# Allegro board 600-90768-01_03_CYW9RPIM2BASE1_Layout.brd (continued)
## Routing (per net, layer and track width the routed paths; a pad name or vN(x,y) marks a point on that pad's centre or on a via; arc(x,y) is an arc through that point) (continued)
SD_CLK: length 34.6
  TOP w0.14: v1(105.46,36.14) 105.86,36.54 J10.57
  BOTTOM w0.14: R18.1 123.75,28.83 120.48,32.1 120.28,32.1 120.01,31.83 119.81,31.83 119.61,32.03 119.61,32.23 119.88,32.5 119.88,32.7 118.11,34.47 110.21,34.47 109.15,35.52 108.57,35.52 108.15,35.1 106.15,35.1 105.46,35.79 v1(105.46,36.14)
SD_CMD: length 36.5
  TOP w0.14: J10.62 111.45,35.74 111.99,35.2 v1(111.99,33.96)
  BOTTOM w0.14: v1(111.99,33.96) 117.09,33.96 117.6,33.45 117.6,32.41 117.98,32.03 117.98,31.84 117.6,31.46 117.6,31.27 117.8,31.07 118,31.07 118.37,31.44 118.57,31.44 118.77,31.24 118.77,31.05 118.39,30.67 118.39,30.48 118.59,30.28 118.79,30.28 119.16,30.65 119.36,30.65 119.56,30.45 119.56,30.26 119.18,29.88 119.18,29.68 119.38,29.49 119.58,29.49 119.95,29.86 120.15,29.86 120.35,29.66 120.35,29.47 119.98,29.09 119.98,28.89 120.17,28.7 120.37,28.7 120.74,29.07 120.94,29.07 121.14,28.87 121.14,28.68 120.77,28.3 120.77,28.1 120.96,27.91 121.16,27.91 121.53,28.28 121.73,28.28 122.68,27.33 122.68,26.49 122.54,26.35 122.16,26.35 122.02,26.21 122.02,25.93 122.16,25.79 122.54,25.79 122.68,25.65 122.68,25.37 122.54,25.23 122.16,25.23 122.02,25.09 122.02,24.81 122.16,24.67 122.54,24.67 122.68,24.53 122.68,24.25 122.54,24.12 122.16,24.12 122.02,23.98 122.02,23.7 122.16,23.56 122.54,23.56 122.68,23.42 122.68,23.14 122.54,23 122.16,23 122.02,22.86 122.02,22.58 122.16,22.44 122.54,22.44 122.68,22.3 122.68,22.02 122.54,21.88 122.26,21.88 122.12,21.74 122.12,21.46 122.26,21.32 122.54,21.32 122.68,21.18 R17.1
SD_DAT0: length 32.2
  TOP w0.14: J10.63 106.54,35.34 v1(106.25,35.64)
  BOTTOM w0.14: v1(106.25,35.64) 108.1,35.64 108.4,35.93 109.3,35.93 109.83,35.4 111.51,35.4 111.94,34.98 118.16,34.98 124.92,28.22 R19.1
SD_DAT1: length 28.2
  TOP w0.14: J10.67 108.87,34.54 109.16,34.25 109.16,33.37 v1(108.92,33.12)
  BOTTOM w0.14: v1(108.92,33.12) 109.7,33.12 110.61,32.22 112.97,32.22 114.17,31.01 115.27,31.01 115.82,30.45 115.82,28.4 119.31,24.92 119.31,24.01 119.17,23.87 118.5,23.87 118.36,23.74 118.36,23.46 118.5,23.32 119.17,23.32 119.31,23.18 119.31,22.9 119.17,22.76 118.5,22.76 118.36,22.62 118.36,22.34 118.5,22.2 119.17,22.2 119.31,22.06 119.31,21.78 119.17,21.64 118.5,21.64 118.36,21.5 118.36,21.22 118.5,21.08 119.17,21.08 119.31,20.94 R20.1
SD_DAT2: length 38.2
  TOP w0.14: J10.69 105.87,34.14 v1(105.77,34.04)
  BOTTOM w0.14: R15.1 120.4,19.88 120.26,20.02 119.85,20.02 119.71,20.15 119.71,20.43 119.85,20.57 120.26,20.57 120.4,20.71 120.4,20.99 120.26,21.13 119.85,21.13 119.71,21.27 119.71,21.55 119.85,21.69 120.26,21.69 120.4,21.83 120.4,22.11 120.26,22.25 119.85,22.25 119.71,22.39 119.71,22.67 119.85,22.81 120.26,22.81 120.4,22.95 120.4,23.23 120.26,23.37 119.85,23.37 119.71,23.51 119.71,23.79 119.85,23.93 120.26,23.93 120.4,24.07 120.4,24.35 120.26,24.49 119.85,24.49 119.71,24.63 119.71,24.9 119.85,25.04 120.26,25.04 120.4,25.18 120.4,25.7 119.8,26.3 119.61,26.3 119.21,25.9 119.01,25.9 118.81,26.09 118.81,26.29 119.21,26.69 119.21,26.89 119.01,27.09 118.82,27.09 118.39,26.66 118.19,26.66 118,26.86 118,27.06 118.42,27.48 118.42,27.68 118.22,27.88 118.03,27.88 117.6,27.45 117.4,27.45 117.21,27.65 117.21,27.85 117.63,28.27 117.63,28.47 117.43,28.67 117.24,28.67 116.81,28.24 116.61,28.24 116.42,28.44 116.42,28.64 116.84,29.06 116.84,29.26 116.32,29.78 116.32,31.38 115.09,32.61 110.77,32.61 109.15,34.23 105.96,34.23 v1(105.77,34.04)
SD_DAT3: length 36.7
  TOP w0.14: v1(105.44,35.13) 105.44,35.46 106.06,36.08 106.46,36.08 106.8,35.74 J10.61
  BOTTOM w0.14: R16.1 121.49,26.77 120.57,27.69 120.37,27.69 119.85,27.18 119.66,27.18 119.46,27.38 119.46,27.58 119.97,28.09 119.97,28.29 119.77,28.49 119.58,28.49 119.04,27.95 118.84,27.95 118.64,28.14 118.64,28.34 119.18,28.88 119.18,29.08 118.98,29.28 118.79,29.28 118.25,28.74 118.05,28.74 117.85,28.93 117.85,29.13 118.39,29.67 118.39,29.87 118.19,30.07 118,30.07 117.46,29.53 117.26,29.53 117.06,29.72 117.06,29.92 117.6,30.46 117.6,30.66 115.26,33 110.93,33 109.32,34.62 105.87,34.62 105.44,35.05 v1(105.44,35.13)
SD_DET: length 37.8
  TOP w0.127: v1(131.9,16.89) 130.99,17.81 130.99,19.48 128.42,22.05 117.53,22.05 117.04,22.53 v1(117.04,22.58) ; J10.76 115.21,32.94 115.72,32.44 115.72,31.57 114.87,30.72 v1(114.87,29.77)
  BOTTOM w0.127: v1(117.04,22.58) 114.87,24.75 v1(114.87,29.77) ; R23.1 133.88,15.98 133.88,16.56 133.55,16.89 v1(131.9,16.89)
SD_PWR: length 21.8
  TOP w0.381: C20.1 124.26,3.5 v1(124.26,2.72)
  L03_PWR w0.508: v1(126.97,13.79) 126.97,8.89 124.28,6.2 124.28,2.74 v1(124.26,2.72)
  BOTTOM w0.508: J17.4 v1(124.26,2.72) ; v1(126.97,13.79) 128.04,14.86 128.04,16.33 128.83,17.12 130,17.12 130.26,17.39 U9.1
SD_PWR_ON: length 40.6
  TOP w0.127: J10.75 106.05,32.94 105.77,33.22 104.98,33.22 104.39,32.64 104.39,30.56 v1(104.06,30.23) ; v1(127.03,21.11) 126.57,21.56 117.07,21.56 v1(117.01,21.63)
  BOTTOM w0.127: R24.2 129.42,22.13 129.23,21.95 U9.4 128.36,21.95 127.86,21.95 v1(127.03,21.11) ; v1(104.06,30.23) 104.06,29.62 104.42,29.26 105.59,29.26 105.94,29.62 111.86,29.62 112.11,29.37 112.47,29.37 112.7,29.59 114.15,29.59 114.62,29.12 114.62,24.02 v1(117.01,21.63)
SDA0: length 71.3
  TOP w0.14: v1(118.62,33.17) 121.13,33.17 122,34.04 123.95,34.04 128.49,38.57 128.49,73.72 129.77,75.01 131.9,75.01 133.72,73.19 U3.1 ; J10.82 111.46,31.74 111.79,32.08 113.36,32.08 113.67,31.78 v1(114.2,31.78)
  L04 w0.112: v1(114.2,31.78) 114.66,32.23 117.68,32.23 v1(118.62,33.17)
TR0_TAP: length 34.4
  TOP w0.127: TP12.1 v1(91.08,57.61)
  BOTTOM w0.127: v1(91.08,57.61) 91.08,58.55 91.77,59.23 91.77,60.58 91.49,60.86 91.49,66.04 90.88,66.65 90.88,71.45 90.16,72.17 90.16,75.94 91.11,76.89 93.1,76.89 94.6,78.39 J11.P11
TR1_TAP: length 30.1
  TOP w0.127: TP10.1 v1(91.06,59.69)
  BOTTOM w0.127: J11.P12 99.65,78.69 94.49,78.69 92.94,77.14 91.01,77.14 89.91,76.04 89.91,72.05 90.58,71.37 90.58,66.55 91.06,66.07 v1(91.06,59.69)
TR2_TAP: length 19.2
  TOP w0.127: TP11.1 v1(90.02,64.74)
  BOTTOM w0.127: J11.P13 94.27,78.93 92.75,77.4 90.87,77.4 89.63,76.17 89.63,71.95 90.32,71.26 90.32,66.42 90.02,66.12 v1(90.02,64.74)
TR3_TAP: length 19.7
  TOP w0.127: TP13.1 v1(88.85,61.77)
  BOTTOM w0.127: v1(88.85,61.77) 88.85,65.31 90.07,66.53 90.07,71.15 89.38,71.84 89.38,76.27 91.5,78.39 J11.P14
TRD0_N: length 38.6
  TOP w0.114: v1(101.96,65.85) 102.21,66.1 102.21,66.38 101.3,67.3 101.3,67.89 101.19,68 U7.4 101.19,69.56 101.3,69.67 101.3,71.42 101.78,71.91 101.78,74.09 102,74.32 102.3,74.47 102.3,74.47 102.3,75.04 J11.P2 ; J10.10 110.65,46.14 110.7,46.1 112.5,46.1 113.39,46.98 113.39,50.67 v1(113.11,50.95)
  L04 w0.102: v1(113.11,50.95) 113.34,51.19 113.34,52.24 102.19,63.39 102.19,65.61 v1(101.96,65.85)
TRD0_P: length 38.6
  TOP w0.114: J10.12 110.64,45.74 110.71,45.82 112.62,45.82 113.67,46.86 113.67,50.7 v1(113.92,50.95) ; v1(102.77,65.85) 102.63,65.85 102.49,65.99 102.49,66.5 101.57,67.41 101.57,67.89 101.69,68.01 U7.5 101.69,69.54 101.57,69.65 101.57,71.31 102.06,71.79 102.06,73.98 102.17,74.09 102.47,74.24 102.47,74.24 102.75,74.15 J11.P1
  L04 w0.102: v1(102.77,65.85) 102.54,65.61 102.54,63.54 113.69,52.39 113.69,51.18 v1(113.92,50.95)
TRD1_N: length 39.6
  TOP w0.114: v1(99.52,65.82) 99.78,66.09 99.78,67.88 99.69,67.98 U7.1 99.69,69.56 99.8,69.67 99.8,70.78 99.21,71.36 99.21,74.55 97.89,75.87 J11.P6 ; v1(111.58,50.98) 111.58,51.13 111.46,51.26 111.09,51.26 110.72,50.89 110.72,49.65 111.99,48.38 111.99,47.44 111.57,47.02 110.72,47.02 110.65,46.94 J10.6
  L04 w0.102: v1(99.52,65.82) 99.73,65.61 99.73,63.81 110.2,53.34 110.2,51.93 110.2,51.64 110.61,51.23 111.33,51.23 v1(111.58,50.98)
TRD1_P: length 39.6
  TOP w0.114: J10.4 110.67,47.34 110.72,47.29 111.45,47.29 111.71,47.55 111.71,48.26 110.44,49.53 110.44,51 110.97,51.54 111.33,51.54 v1(111.58,51.79) ; v1(100.35,65.82) 100.19,65.82 100.06,65.95 100.06,67.88 100.19,68 U7.2 100.19,69.54 100.08,69.65 100.08,70.89 99.49,71.48 99.49,74.73 99.76,74.99 100.65,74.99 100.91,74.73 100.91,73.63 J11.P3
  L04 w0.102: v1(111.58,51.79) 111.37,51.58 110.75,51.58 110.55,51.79 110.55,53.49 100.08,63.96 100.08,65.72 100.18,65.82 v1(100.35,65.82)
TRD2_N: length 41.1
  TOP w0.114: v1(96.58,67.35) 96.29,67.06 95.75,67.06 95.58,67.24 95.58,67.89 95.69,68.01 U6.5 95.69,69.54 95.55,69.67 95.55,70.21 96.85,71.5 96.85,74.22 96.05,75.02 95.47,75.02 95.19,74.88 94.68,75.05 J11.P8 ; v1(107.72,50.95) 108,50.67 108,48.92 108.76,48.15 108.76,46.23 108.6,46.07 108.4,46.07 108.33,46.14 J10.9
  L04 w0.102: v1(96.58,67.35) 96.4,67.18 95.87,67.18 95.51,66.82 95.51,65.72 95.68,65.55 95.68,65.55 95.93,65.3 95.93,65.3 107.88,53.35 107.88,51.11 v1(107.72,50.95)
TRD2_P: length 41
  TOP w0.114: v1(108.53,50.95) 108.28,50.7 108.28,49.03 109.04,48.27 109.04,46.12 108.72,45.79 108.37,45.79 108.33,45.74 J10.11 ; J11.P7 95.05,74.31 95.13,74.54 95.53,74.75 95.93,74.75 96.57,74.11 96.57,71.62 95.28,70.32 95.28,69.65 95.19,69.56 U6.4 95.19,68 95.3,67.89 95.3,67.12 95.64,66.78 96.32,66.78 v1(96.58,66.52)
  L04 w0.102: v1(96.58,66.52) 96.27,66.83 96.01,66.83 95.86,66.67 95.86,65.87 96.28,65.45 96.28,65.44 108.23,53.49 108.23,51.26 v1(108.53,50.95)
TRD3_N: length 39.8
  TOP w0.114: v1(94.35,66.45) 94.08,66.72 94.08,67.89 94.19,68 U6.2 94.19,69.54 94.11,69.62 94.11,72.36 94.42,72.68 94.42,74.11 93.82,74.71 92.41,74.71 92.29,74.76 J11.P10 ; J10.5 107.01,46.94 106.96,46.99 105.98,46.99 104.67,48.3 104.67,50.94 105.09,51.36 105.77,51.36 v1(106.02,51.61)
  L04 w0.102: v1(94.35,66.45) 94.13,66.24 94.13,65.27 105.01,54.39 105.01,51.75 105.35,51.41 105.82,51.41 v1(106.02,51.61)
TRD3_P: length 39.9
  TOP w0.114: J10.3 107.01,47.34 106.93,47.27 106.1,47.27 104.95,48.41 104.95,50.82 105.21,51.08 105.74,51.08 v1(106.02,50.8) ; J11.P9 92.21,73.33 92.1,73.44 92.1,74.31 92.21,74.42 93.7,74.42 94.14,73.98 94.14,72.79 93.83,72.48 93.83,69.7 93.69,69.56 U6.1 93.69,68.01 93.8,67.89 93.8,66.72 v1(93.53,66.45)
  L04 w0.102: v1(106.02,50.8) 105.75,51.07 105.21,51.07 104.66,51.61 104.66,54.24 93.78,65.12 93.78,66.2 v1(93.53,66.45)
TXD: length 129.4
  TOP w0.14: R96.2 v1(72.25,33.54)
  L04 w0.112: v1(72.25,33.54) 71.96,33.25 71.96,29.92 71.22,29.18 69.8,29.18 68.41,27.8 42.06,27.8 40.89,26.63 36.37,26.63 35.59,25.84 28.73,25.84 27.68,26.88 18.04,26.88 18.03,26.88 15.57,26.88 12.38,30.07 12.38,59.4 19.78,66.79 19.78,75.56 22.68,78.46 22.68,81.38 23.3,82 v1(23.3,84.16)
  BOTTOM w0.14: U16.23 v1(23.3,84.16)
UART_CTS: length 98.5
  TOP w0.127: SW4.4 SW4.3 v1(9.94,47.5) ; J23.36 54.87,33.16 58.27,29.77 71.88,29.77 72.33,30.21 72.78,30.21 74.6,32.03 74.6,40.5 J30.8
  TOP w0.14: v1(11.2,48.76) 12.34,47.62 33.88,47.62 40.03,41.48 46.71,41.48 48.23,39.95 54.46,39.95 54.87,39.54 J23.36
  BOTTOM w0.14: v1(9.94,47.5) v1(11.2,48.76)
USB2_N: length 82.1
  TOP w0.127: v1(136.98,52.78) 136.73,52.53 136.73,50.37 139.83,47.27 140.54,47.27 140.62,47.34 J5.3
  L05 w0.094: v1(72.98,59.02) 73.23,58.78 73.23,55.88 77.88,51.23 101,51.23 102.6,49.63 113.5,49.63 114.03,49.1 129.9,49.1 132.74,51.95 136.45,51.95 136.75,52.25 136.75,52.55 v1(136.98,52.78)
  BOTTOM w0.127: v1(72.98,59.02) 73.27,59.31 73.27,60.14 73.26,60.15 73.26,60.27 73.14,60.38 U1.4
USB2_P: length 82.1
  TOP w0.127: J5.5 140.62,46.94 140.55,47.02 139.72,47.02 136.47,50.26 136.47,52.6 136.3,52.78 v1(136.17,52.78)
  L05 w0.094: v1(73.81,59.02) 73.48,58.7 73.48,55.95 77.97,51.46 101.09,51.46 101.12,51.43 101.15,51.43 102.72,49.86 113.59,49.86 114.12,49.33 129.8,49.33 132.65,52.17 136.36,52.17 136.53,52.34 136.53,52.65 136.4,52.78 v1(136.17,52.78)
  BOTTOM w0.127: v1(73.81,59.02) 73.52,59.3 73.52,60.27 73.64,60.38 U1.3
USB-UART_VBUS: length 26.4
  TOP w0.254: J47.A9 38.06,82.18 J47.B4 ; J47.A4 40.56,82.18 J47.B9
  TOP w0.305: U29.18 v1(39.52,74.59)
  TOP w0.381: 30.29,76.45 D21.1 ; D21.1 30.29,79.31 ; D21.1 31.82,77.88 ; 24.66,56.91 R302.1 24.13,57.46 ; 25.81,56.56 C144.1 26.54,57.21 ; D26.A v1(47.35,74.88) ; 20.8,55.78 U35.7 23.14,55.78 ; 20.8,57.05 U35.8 23.14,57.05
  L03_PWR w0.381: 41.19,82.23 J47.B9 40.51,81.55 ; 37.77,81.48 J47.B4 38.11,81.55
  BOTTOM w0.381: C172.2 38.18,77.7 ; C172.2 38.18,74.44 ; C172.2 39.11,76.07 ; 41.1,81.65 J47.B9 41.19,82.23
  vias: v1(23.67,56.31) v1(24.18,55.63) v1(24.79,56.29) v1(25.22,55.58) v1(25.76,56.29) v1(40.56,77.5) v1(41.58,78.23) v1(41.58,77.44) v1(42.49,78.03)
USB_PWR: length 71.2
  TOP w0.305: J1.B4 118.46,82.18 J1.A9 ; J1.B9 120.96,82.18 J1.A4
  TOP w0.381: 122.01,76.38 D29.K ; D29.K 122.59,77.06 ; D29.K 122.59,75.7 ; D32.C 120.86,74.97 ; D32.C 120.86,72.81 ; D32.C 122.49,73.89 ; D32.C 119.23,73.89 ; C41.2 121.93,70.59 ; C41.2 120.07,70.59 ; C41.2 121,72.22 ; C41.2 121,68.96
  L03_PWR w0.381: v1(76.83,65.86) 77.85,64.85 79.32,64.85 79.81,65.33 79.81,66.55 80.87,67.61 91.49,67.61 92.72,68.84 105.61,68.84 107.17,70.41 108.71,70.41 110.19,71.88 112.74,71.88 113.32,71.3 117.32,71.3 v1(119.43,69.19)
  L04 w0.381: 118.16,81.48 J1.B4 118.51,81.55 ; 120.91,81.55 J1.B9 121.59,82.23
  BOTTOM w0.381: R1.1 76.87,65.83 v1(76.83,65.86)
  vias: v1(119.46,68.02) v1(120.65,68.02) v1(121.51,77.24) v1(121.79,67.97) v1(121.87,78) v1(122.66,77.62)
USBOTG: length 78.1
  TOP w0.127: J5.1 140.93,47.74 140.34,48.34 140.34,50.93 136.47,54.79 v1(135.08,54.79)
  BOTTOM w0.127: U1.2 74.14,60.03 74.34,59.83 74.92,59.83 75.48,60.4 R1.2 R2.1 76.02,58.5 79.2,55.32 91.06,55.32 92.46,53.92 102.62,53.92 104.06,55.37 114.53,55.37 115.11,55.96 117.63,55.96 118.57,55.02 134.85,55.02 v1(135.08,54.79)
USBRPI_DM: length 22
  TOP w0.127: U30.2 39.19,79.33 39.19,79.53 38.96,79.76 v1(38.9,79.76) 39.18,80.04 39.18,80.4 39.06,80.52 J47.A7
  BOTTOM w0.127: J47.B7 39.45,81.97 39.45,81.79 41.16,80.08 41.16,79.32 40.66,78.82 39.54,78.82 39.19,79.16 39.19,79.46 v1(38.9,79.76) 38.96,79.76 39.2,79.99 39.2,80.23 39.01,80.42 37.72,80.42 37.12,79.82 36.74,79.82 36.62,79.69 36.23,79.69 36.11,79.82 35.73,79.82 35.6,79.69 35.22,79.69 35.09,79.82 34.32,79.82 33.88,80.26 33.7,80.26 33.43,80.53 33.43,80.71 32.92,81.22 32.92,82.25 32.38,82.79 29.9,82.79 29.78,82.66 U16.11
USBRPI_DP: length 21.9
  TOP w0.127: U30.1 39.45,79.33 39.45,79.55 39.65,79.76 v1(39.74,79.76) 39.45,80.05 39.45,80.39 39.56,80.51 J47.A6
  BOTTOM w0.127: J47.B6 39.07,82.23 39.19,82.1 39.19,81.5 39.1,81.4 39.1,81.17 39.22,81.04 39.46,81.04 39.55,81.14 39.73,81.14 40.9,79.97 40.9,79.42 40.55,79.07 39.64,79.07 39.45,79.26 39.45,79.63 39.58,79.76 v1(39.74,79.76) 39.45,80.04 39.45,80.34 39.12,80.67 37.62,80.67 37.02,80.07 34.43,80.07 33.17,81.33 33.17,82.35 32.48,83.04 29.91,83.04 29.79,83.16 U16.10
WL_HOST_WAKE: length 61.4
  TOP w0.127: R37.1 52.09,47.34 51.12,46.37 J23.21 51.12,44.75 v1(49.89,43.51)
  BOTTOM w0.127: J35.5 20.42,47.35 29.87,47.35 30.28,46.94 30.28,41.47 31.83,39.91 31.83,37.61 36.57,32.87 48.21,32.87 52.76,37.41 52.76,39.85 53.03,40.12 53.03,41.03 52.02,42.04 50.9,42.04 49.89,43.05 v1(49.89,43.51)
WL_JTAG_TCK: length 53
  TOP w0.14: v1(57.38,34.49) 57.4,34.52 57.4,34.92 57.37,34.95 J23.46
  BOTTOM w0.14: J38.9 18.59,41.45 27.91,41.45 30.15,39.21 30.15,36.91 36.06,31 50.93,31 54.42,34.49 v1(57.38,34.49)
WL_JTAG_TDI: length 51.1
  TOP w0.14: J23.40 55.87,36.08 56.01,35.94 56.25,35.94 56.39,35.8 56.39,35.52 56.25,35.39 56.01,35.39 55.87,35.25 55.87,34.38 56.01,34.25 v1(56.01,33.38)
  BOTTOM w0.14: v1(56.01,33.38) 56.01,32.97 55.37,32.34 55.37,32.14 56.28,31.23 56.28,31.03 56.08,30.84 55.89,30.84 54.98,31.74 54.78,31.74 54.58,31.54 54.58,31.35 55.49,30.44 55.49,30.24 55.29,30.04 55.09,30.04 54.19,30.95 53.99,30.95 52.86,29.82 35.57,29.82 28.97,36.42 28.97,38.72 27.5,40.18 24.94,40.18 J38.3
WL_JTAG_TDO: length 51.2
  TOP w0.14: J23.38 v1(55.37,33.58)
  BOTTOM w0.14: J38.5 22.83,40.61 27.64,40.61 29.36,38.89 29.36,36.58 35.73,30.21 51.32,30.21 52.23,31.13 52.43,31.13 52.92,30.64 53.12,30.64 53.31,30.84 53.31,31.03 52.83,31.52 52.83,31.72 53.02,31.92 53.22,31.92 53.71,31.43 53.91,31.43 54.11,31.63 54.11,31.82 53.62,32.31 53.62,32.51 53.81,32.71 54.01,32.71 54.5,32.22 54.7,32.22 54.9,32.42 54.9,32.61 54.41,33.1 54.41,33.3 54.69,33.58 v1(55.37,33.58)
WL_JTAG_TMS: length 51.3
  TOP w0.14: J23.48 57.87,34.02 v1(57.78,33.93)
  BOTTOM w0.14: v1(57.78,33.93) 57.71,34.01 55.57,34.01 55.5,34.09 54.58,34.09 51.1,30.61 35.9,30.61 29.76,36.75 29.76,39.05 27.76,41.05 20.73,41.05 J38.7
WL_JTAG_TRST: length 42.8
  TOP w0.14: v1(56.87,33.55) J23.44
  BOTTOM w0.14: J38.1 28.57,36.6 28.57,36.26 35.41,29.43 55.92,29.43 56.87,30.38 v1(56.87,33.55)
WL_NDIS: length 23.8
  TOP w0.127: v1(106.81,23.24) 108.62,25.06 108.62,29.94 108.41,30.15 107.52,30.15 J10.89 ; SW8.3 v1(104.72,10.74)
  BOTTOM w0.127: v1(104.72,10.74) 104.01,11.46 104.01,20.45 v1(106.81,23.24)
WL_REG_ON_3P3: length 136.7
  TOP w0.127: SW8.7 99.64,10.41 99.29,10.77 97.66,10.77 97.51,10.62 97.51,7.32 96.52,6.32 91.19,6.32 86.11,11.4 v1(86.11,13.92) 86.94,13.92 87.3,13.56 88.45,13.56 R38.2 90.08,13.58 R31.2 ; v1(61.29,33.99) 61.29,34.7 60.27,35.71 60.27,36.4 59.87,36.8 J23.56 ; v1(62.29,26.83) 39.19,26.83 38.54,27.48 14.25,27.48 12.8,28.93 12.8,32.51 12.42,32.89 12.42,35.86 11.51,36.77 SW3.3 SW3.4
  BOTTOM w0.127: v1(86.11,13.92) 83.19,13.92 75.16,21.95 71.21,21.95 67.32,25.83 65.23,25.83 64.23,26.83 v1(62.29,26.83) 62.29,30.87 61.62,31.53 61.62,33.65 v1(61.29,33.99)
WL_UART_CTS: length 61.8
  TOP w0.127: R54.2 68.61,34.09 64.18,34.09 62.61,35.65 v1(62.61,36.2) 62.37,36.44 J23.66
  BOTTOM w0.127: v1(62.61,36.2) 61.68,36.2 61.37,35.89 54.17,35.89 54.15,35.87 54.14,35.87 50.58,32.31 36.41,32.31 31.32,37.4 31.32,39.7 29.77,41.26 29.77,46.43 29.59,46.61 24.77,46.61 J35.3
WL_UART_RTS: length 54.9
  TOP w0.127: J23.62 61.37,36.78 v1(61.09,36.5)
  BOTTOM w0.127: J35.4 22.61,46.99 29.69,46.99 30.02,46.66 30.02,41.36 31.58,39.81 31.58,37.5 36.52,32.56 50.47,32.56 54.04,36.13 54.04,36.13 54.22,36.3 60.89,36.3 v1(61.09,36.5)
WL_UART_RXD: length 80
  TOP w0.14: v1(68.45,42.8) 67.54,41.88 64.14,41.88 63.63,41.38 63.63,40.34 63.37,40.08 J23.70 63.37,36.86 63.64,36.59 v1(63.64,36.28)
  BOTTOM w0.14: v1(63.64,36.28) 62.83,35.48 61.18,35.48 61.17,35.48 57.76,35.48 57.75,35.49 54.31,35.49 54.31,35.48 54.3,35.48 50.61,31.79 36.39,31.79 30.94,37.24 30.94,39.54 29.38,41.1 29.38,46.07 29.27,46.18 26.87,46.18 J35.2 ; v1(68.45,42.8) 70.31,42.8 71.79,41.32 82.76,41.32 83.13,40.94 85.87,40.94 86.01,41.09 R57.2
WL_UART_TXD: length 54.8
  TOP w0.14: J23.68 62.87,36.7 63.09,36.48 63.09,36.01 63.98,35.13 v1(63.98,35.13) 67.84,35.13 68.03,34.94 R55.2
  BOTTOM w0.14: v1(63.98,35.13) 63.04,35.13 63,35.08 61.02,35.08 61.01,35.09 54.46,35.09 50.77,31.39 36.22,31.39 30.54,37.07 30.54,39.38 28.27,41.65 J35.1
N17441828: length 1.6
  BOTTOM w0.508: U2.5 80.73,68.56 R4.1
N17442267: length 15.9
  BOTTOM w0.127: U14.31 64.97,60.46 65.13,60.3 65.13,59 66.06,58.06 69.77,58.06 71.8,60.1 71.8,62.84 73.14,64.18 U1.7
N17442276: length 14.8
  BOTTOM w0.127: U1.6 72.64,64.06 71.53,62.94 71.53,60.25 69.63,58.36 66.16,58.36 65.47,59.05 U14.30
N17442959: length 9.6
  BOTTOM w0.127: Y1.3 60.28,54.95 61.32,55.98 63.6,55.98 63.94,56.32 63.94,58.47 63.67,58.74 C8.1 63.67,59.61 64.47,60.4 U14.32
N17443006: length 9.6
  BOTTOM w0.127: Y1.1 61.98,56.93 62.5,56.41 63.45,56.41 63.58,56.54 63.58,56.82 63.42,56.97 62.99,56.97 62.89,57.07 62.89,57.33 63.02,57.45 63.4,57.45 63.52,57.58 63.52,57.78 63.42,57.89 63.09,57.89 62.99,57.99 62.99,58.17 63.14,58.32 63.37,58.32 63.45,58.4 63.45,58.6 63.23,58.81 62.88,58.81 62.76,58.93 C7.1 62.76,59.79 63.17,60.2 63.63,60.2 63.97,60.54 U14.33
N17443696: length 3.1
  BOTTOM w0.127: R3.2 60.89,60.15 62.43,60.15 62.97,60.68 U14.35
N17444208: length 1.8
  BOTTOM w0.127: U14.24 68.17,63.4 68.32,63.25 R6.1
N17444213: length 2.6
  BOTTOM w0.127: U14.22 67.91,64.4 69.03,65.51 R7.1
N17444218: length 1.7
  BOTTOM w0.305: R8.1 67.46,59.97 66.47,60.96 U14.28
N17444223: length 1.9
  BOTTOM w0.127: R10.1 68.49,62.37 67.96,62.9 U14.25
N17463017: length 7.5
  TOP w0.127: C53.1 97.38,70.59 98.08,71.28 J11.P5
  BOTTOM w0.127: J11.P4 98.08,74.6 J11.P5
N17463374: length 30.8
  TOP w0.127: R13.2 91.05,69.17 89.89,70.33 v1(88.87,70.33)
  BOTTOM w0.127: v1(88.87,70.33) 88.67,70.33 88.09,70.92 88.09,76.91 88.36,77.18 88.36,78.17 88.09,78.44 88.09,82.43 90.53,84.88 100.14,84.88 J11.P16
N17463377: length 20.8
  TOP w0.127: R14.2 90.11,69.51 89.94,69.67 v1(89.15,69.67)
  BOTTOM w0.127: J11.P18 90.8,85.65 87.83,82.68 87.83,78.64 87.15,77.95 87.15,77.24 87.83,76.56 87.83,70.71 88.87,69.67 v1(89.15,69.67)
N17465158: length 1.5
  TOP w0.203: R21.1 137.91,9.1 D14.C
N17465213: length 6.2
  TOP w0.203: v1(132.28,8.26) 132.28,9.3 U8.4 ; v1(135.48,8.64) 135.94,9.09 R21.2
  BOTTOM w0.203: v1(132.28,8.26) 135.1,8.26 v1(135.48,8.64)
N17469381: length 3.5
  BOTTOM w0.127: J17.9 131.55,15.68 131.85,15.98 R23.2
N17469410: length 3.4
  BOTTOM w0.127: J17.10 133.01,15.02 R22.2
N17494894: length 2.8
  TOP w0.155: J23.53 59.12,47.22 59.59,47.69 R50.1
N17494904: length 2.9
  TOP w0.127: R46.1 57.78,48.06 58.06,47.78 58.06,47.4 57.73,47.06 57.73,46.59 57.62,46.48 J23.47
N17494909: length 2.9
  TOP w0.127: R47.1 58.61,48.04 58.34,47.78 58.34,47.28 58.01,46.95 58.01,46.59 58.12,46.48 J23.49
N17494920: length 2.8
  TOP w0.127: R40.1 54.47,48.1 54.73,47.83 54.73,46.59 54.62,46.48 J23.35
N17494923: length 2.8
  TOP w0.127: J23.37 55.12,46.48 55.01,46.59 55.01,47.8 55.29,48.08 R41.1
N17494926: length 2.8
  TOP w0.127: R42.1 56.12,48.07 56.36,47.83 56.36,47.32 56.23,47.19 56.23,46.59 56.12,46.48 J23.41
N17494929: length 2.9
  TOP w0.127: R43.1 56.95,48.04 56.64,47.73 56.64,47.21 56.51,47.08 56.51,46.59 56.62,46.48 J23.43
N17499052: length 2.7
  TOP w0.155: R28.1 48.12,46.64 J23.9
N17499057: length 2.6
  TOP w0.155: R29.1 47.85,47.4 48.62,46.63 J23.11
N17499218: length 2.4
  TOP w0.155: J23.13 49.12,46.86 48.69,47.3 R30.1
N17499237: length 2.3
  TOP w0.155: J23.15 49.62,47.65 R32.1
N17499256: length 2.3
  TOP w0.155: R35.1 50.39,46.91 50.12,46.64 J23.17
N17499275: length 2.5
  TOP w0.155: J23.19 50.62,46.48 51.25,47.11 R36.1
N17499655: length 14.6
  TOP w0.155: R49.2 68.46,32.22 67.97,32.72 60.81,32.72 59.36,34.16 59.36,35.79 58.87,36.28 J23.52
N17504773: length 1.3
  TOP w0.127: D15.A 33.27,7.33 R58.2
N17512684: length 5.8
  BOTTOM w0.381: R64.1 35.51,21.15 U12.5 33.42,18.69 R61.2 R62.2
N17512777: length 2.3
  BOTTOM w0.381: C35.1 35.52,26.49 34.62,26.49 34.27,26.14 U12.4
N17512799: length 1.5
  BOTTOM w0.381: U12.1 29.58,26.17 C27.1
N17512803: length 0.9
  BOTTOM w0.381: R60.1 C27.2
N17512813: length 21.3
  TOP w0.381: v1(27.19,25.41) 27.84,24.77 27.84,21.87 30.05,19.66 v1(30.05,16.33)
  BOTTOM w0.381: 28.93,21.15 U12.8 29.61,20.12 ; L1.1 29.58,16.29 ; L1.1 26.67,16.29 ; L1.1 28.13,19.12 ; L1.1 28.13,13.46 ; R60.2 v1(27.19,25.41)
N17512829: length 2.7
  BOTTOM w0.381: U12.6 32.15,19.84 C229.1 32.16,19.41 R63.1
N17540958: length 16.9
  TOP w0.254: v1(95.66,16.51) 95.23,16.08 U10.7
  TOP w0.305: v1(94.87,11.68) 95.56,11.68 96.02,12.15 R26.1 C21.2 95.97,13.58 U10.2 ; v1(91.72,13.36) 91.94,13.58 U10.15 ; U10.1 93.85,12.63 v1(94.09,12.38)
  BOTTOM w0.508: v1(94.87,11.68) 94.79,11.68 v1(94.09,12.38) 92.22,12.38 91.72,12.89 v1(91.72,13.36) 91.72,14.45 93.78,16.51 v1(95.66,16.51)
N17540970: length 2.2
  TOP w0.305: R27.1 C22.1 93.32,12.06 93.35,12.09 U10.16
N17541044: length 1.7
  TOP w0.127: R31.1 90.96,13.58 91.47,14.08 U10.14
N17541046: length 1.5
  TOP w0.127: R33.1 90.96,14.58 U10.13
N17541095: length 1.7
  TOP w0.127: U10.12 91.45,15.08 90.99,15.54 R34.1
N17548832: length 50.8
  TOP w0.127: J23.8 47.87,36.66 57.23,27.3 81.32,27.3 85.45,31.42 85.45,31.42 89.14,35.12 J25.2
N17548852: length 51.2
  TOP w0.127: J25.4 80.16,27.55 57.45,27.55 48.37,36.63 J23.10
N17549259: length 16.6
  TOP w0.127: J23.50 58.37,33.02 60.05,31.34 67.87,31.34 68.27,30.94 R48.2
N17549874: length 8.7
  TOP w0.127: SW2.1 v1(5.79,22.72) SW2.2
  BOTTOM w0.127: R44.2 5.79,23.4 v1(5.79,22.72)
N17549924: length 8.9
  TOP w0.127: SW3.2 1.98,32.26 v1(5.79,32.26) 9.93,32.26 SW3.1
  BOTTOM w0.127: v1(5.79,32.26) R45.2
N17560700: length 3.1
  TOP w0.127: J23.23 51.62,46.44 52.22,47.04 52.73,47.04 52.97,47.28 R39.1
N17563208: length 8.8
  TOP w0.127: SW4.2 5.84,41.81 v1(5.84,41.81) 9.94,41.81 SW4.1
  BOTTOM w0.127: v1(5.84,41.81) R52.2
N17565806: length 52.1
  TOP w0.127: J23.12 48.87,36.53 57.6,27.81 77.43,27.81 83.6,33.97 83.6,34.03 87.4,37.84 87.4,38.71 88.89,40.2 J25.6
N17565868: length 53.5
  TOP w0.127: J25.8 88.63,41.1 87.81,41.1 86.84,40.13 86.84,37.83 83.34,34.33 83.34,34.08 77.33,28.06 57.75,28.06 49.37,36.44 J23.14
N17568318: length 21.2
  BOTTOM w0.14: R15.2 120.4,17.55 114.63,11.79 114.63,7.59 118.37,3.85 J17.1
N17568347: length 22.7
  BOTTOM w0.14: J17.2 122.06,4.76 121.87,4.95 118.01,4.95 115.06,7.9 115.06,11.51 118.9,15.34 119.23,15.34 121.49,17.6 R16.2
N17568375: length 22.8
  BOTTOM w0.14: R17.2 122.66,18.5 122.66,17.48 119.91,14.73 119.02,14.73 116.84,12.55 116.84,6.68 118.14,5.38 122.61,5.38 123.16,4.83 J17.3
N17568415: length 24.9
  BOTTOM w0.14: J17.5 125.36,4.92 124.46,5.82 118.34,5.82 117.37,6.78 117.37,12.37 119.1,14.1 120.37,14.1 123.75,17.48 R18.2
N17569067: length 27.2
  BOTTOM w0.14: J17.7 127.56,5.43 126.75,6.25 118.75,6.25 117.86,7.14 117.86,12.04 119.43,13.61 120.9,13.61 124.92,17.63 R19.2
N17569095: length 31.2
  BOTTOM w0.14: R20.2 119.31,17.2 114.17,12.06 114.17,7.42 119.51,2.08 127.13,2.08 127.71,2.67 128.37,2.67 128.66,2.96 J17.8
N17573256: length 2.9
  BOTTOM w0.381: R62.1 34.57,16.39 35.03,15.92 SW5.3
N17579667: length 10.9
  TOP w0.127: U3.5 147.71,71.24 148.34,70.61 148.34,66.63 J9.4
N17579869: length 12.7
  TOP w0.127: J9.3 151.6,65.85 149.81,67.64 149.81,70.56 148.49,71.88 146.36,71.88 U3.6 145.5,71.89 144.96,71.34 R11.2
N17596444: length 36.9
  TOP w0.127: J23.34 54.37,33.22 58.13,29.46 71.98,29.46 72.47,29.95 72.92,29.95 74.9,31.92 74.9,38.26 J30.6
N17596453: length 35.3
  TOP w0.127: J30.4 75.18,36.01 75.18,31.8 73.03,29.64 72.54,29.64 72.07,29.17 57.97,29.17 53.87,33.26 J23.32
N17596462: length 35.2
  TOP w0.127: J30.2 75.92,34.2 75.92,31.14 74.1,29.32 72.6,29.32 72.16,28.88 57.78,28.88 51.37,35.29 J23.22
N17603435: length 4.7
  TOP w0.381: v1(82.52,60.61) 82.55,60.63 v1(84.1,60.63)
  BOTTOM w0.381: v1(84.1,60.63) 84.1,60.25 83.91,60.06 U15.1 ; v1(82.52,60.61) R69.1 C52.2
N17603462: length 6.6
  BOTTOM w0.381: U15.6 83.01,57.32 82.26,58.07 82.26,59.15 83.48,60.36 R70.1
  BOTTOM w0.508: R70.1 C51.1
N17711071: length 2.7
  BOTTOM w0.381: SW5.1 33.19,15.92 33.51,16.24 R61.1
N17724540: length 3.6
  BOTTOM w0.127: R82.2 72.85,18.51 C55.1 R85.1 72.83,16.13 C57.1
N17724607: length 3.3
  BOTTOM w0.127: C58.1 R84.1 69.07,17.14 C56.1 69.07,19.42 R83.2
N17727243: length 20.3
  BOTTOM w0.127: C57.2 70.87,14.66 U18.2 72.63,14.64 76.66,10.62 83.77,10.62 85.29,9.09 85.29,7.01 J46.3
N17727252: length 10.5
  TOP w0.127: v1(69.58,14.64) v1(74.33,14.64)
  BOTTOM w0.127: v1(69.58,14.64) U18.1 70.16,15.34 69.93,15.57 69.93,16.1 C58.2 ; v1(74.33,14.64) 77.74,14.64 J46.2
N17754557: length 15.9
  TOP w0.127: TP33.1 39.09,60.81 39.09,62.03 44.4,67.34 44.4,70.97 44.02,71.34 U29.7
N17754588: length 13
  TOP w0.127: U29.8 44.18,71.84 44.68,71.34 44.68,67.06 40.01,62.38 TP34.1
N17760781: length 20.7
  TOP w0.381: C144.2 25.56,58.31 R302.2 v1(23.84,58.31) ; R297.1 23.71,50.03 C139.2 22.53,51.21 v1(22.48,51.26) 22.13,51.61 20.56,51.61 19.78,52.38 R321.1
  BOTTOM w0.381: v1(23.84,58.31) 22.48,56.95 v1(22.48,51.26)
N17761001: length 1.4
  BOTTOM w0.127: Q14.D 46.48,68.82 R373.1
N17761005: length 2.6
  TOP w0.127: v1(48.18,68.81) 48.18,69.41 D26.C
  BOTTOM w0.127: R373.2 v1(48.18,68.81)
N17763457: length 1.4
  BOTTOM w0.508: C210.1 38.57,44.01 U33.14
N17763461: length 7.5
  BOTTOM w0.254: 39.38,42.76 C210.2
  BOTTOM w0.381: 37.4,36.21 L5.1 ; L5.1 35.77,37.59 ; L5.1 37.4,38.97
  BOTTOM w0.508: U33.13 39.38,42.76 ; C210.2 39.42,42.04
N17763467: length 7.5
  BOTTOM w0.381: L5.2 42.5,38.97 ; L5.2 42.5,36.21 ; L5.2 44.13,37.59
  BOTTOM w0.508: 40.79,42.03 C197.2 U33.12
N17763564: length 1.4
  BOTTOM w0.508: U33.11 41.63,43.97 C197.1
N17763650: length 23.3
  L03_PWR w0.381: v1(41.25,49.43) 41.25,48.74 39.7,47.19 35.56,47.19 v1(35.31,46.94)
  BOTTOM w0.381: 41.98,48.87 C195.1 ; C195.1 41.98,49.93 ; C195.1 41.42,49.4 ; 43.6,62.09 R383.1 42.67,63.07 ; C192.1 41.87,54.32 ; C192.1 41.87,52.36 ; C192.1 41.09,53.34 ; 41.87,50.2 C191.1 ; C191.1 41.87,52.16 ; C191.1 41.09,51.18 ; 41.02,58.01 C185.P ; C185.P 43.05,59.09 ; C185.P 43.05,56.93 ; R399.1 34.98,47.26 v1(35.31,46.94)
  BOTTOM w0.508: U33.3 41.49,48.7
N17763766: length 4.8
  BOTTOM w0.229: U33.15 36.56,44.5 ; 36.56,44.5 36.56,45.2 36.86,45.49 37.7,45.49 U33.17 ; 36.56,44.5 C224.2
N17763790: length 3
  BOTTOM w0.254: R399.2 36.65,47.73 36.88,47.5 U33.21
  BOTTOM w0.305: R399.2 R403.1
N17763820: length 2.8
  BOTTOM w0.229: C225.2 36.54,46 U33.18
N17763850: length 1.5
  BOTTOM w0.229: R384.2 43.25,45.09 43.15,45 U33.9
N17767575: length 7.9
  TOP w0.127: J1.A5 120.46,80.05 121.18,79.32 124.99,79.32 125.91,78.41 R404.2
N17767581: length 15.1
  TOP w0.127: R65.2 v1(116.38,78.46)
  L04 w0.127: J1.B5 118.91,83.93 118.36,84.48 114.15,84.48 113.56,83.9 113.56,80.01 115.11,78.46 v1(116.38,78.46)
N17769646: length 18.2
  TOP w0.127: U29.12 45.23,73.84 46,73.08 46,66.45 43.94,64.39 43.94,61.85 42.6,60.5 TP37.1
N17769649: length 16.3
  TOP w0.127: TP36.1 45.19,65.24 46.28,66.33 46.28,73.43 45.14,74.57 45.14,74.59 U29.13
N17801368: length 4.9
  TOP w0.127: J5.6 144.12,46.99 144.72,46.99 144.86,47.13 144.86,47.13 145.65,47.93 146.73,47.93 146.73,47.92 147.6,47.92 R406.2
N17848252: length 3.8
  TOP w0.127: R408.1 15.59,67.96 16.4,68.77 SW10.1
N17848257: length 2.2
  TOP w0.127: SW10.5 16.4,74.8 R400.2
N17849598: length 2.2
  TOP w0.127: R398.2 21.4,74.8 SW10.7
N17880549: length 1.1
  BOTTOM w0.381: C36.1 R63.2
N174866950: length 1.8
  TOP w0.203: R12.1 137.19,4.15 D13.C

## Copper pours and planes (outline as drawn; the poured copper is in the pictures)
1.8V on L03_PWR: 111.3,30.58 111.96,30.58 112.67,29.87 112.67,29.74 112.27,29.34 111.3,29.34 111.07,29.57 111.07,30.35
3.3V on L03_PWR: outline of 92 points within 52.4,9.96 132.36,88.24 ; 4 cut-outs
5V_IN on BOTTOM: 34.9,68.25 38.46,68.25 38.81,67.89 38.81,67.18 38.53,67.18 38.35,67.01 38.35,66.73 38.63,66.73 39.73,65.63 41.88,65.63 42.04,65.48 42.04,64.16 39.79,61.91 39.79,49.47 38.89,48.56 38.89,45.52 38.86,45.49 38.4,45.49 38.38,45.52 38.38,47.98 38.28,48.08 38.48,48.29 38.48,48.44 38.1,48.44 38.02,48.51 38.02,49.58 37.72,49.89 37.72,54.2 35.64,56.29 35.64,63.12 34.52,64.24 34.52,67.87 ; 3 cut-outs
GND on L03_PWR: 148.79,89.66 149.1,89.36 149.1,88.8 149.81,88.8 150.52,89.51 150.4,89.63 153.15,88.26 154.42,85.46 154.33,85.55 153.62,84.84 153.62,84 154.23,84 154.43,83.79 154.43,5.08 153.09,1.85 149.86,0.51 5.08,0.51 1.85,1.85 0.51,5.08 0.51,85.09 1.85,88.32 5.08,89.66 ; 16 cut-outs
GND_EARTH on BOTTOM: 32.08,89.59 126.36,89.59 126.92,89.03 126.92,85.34 125.73,84.15 125.73,82.02 125.07,81.36 123.75,81.36 123.24,81.86 123.24,82.52 123.29,82.47 123.55,82.47 123.6,82.52 123.6,82.73 123.39,82.73 123.24,82.88 123.23,82.87 122.3,83.79 113.03,83.79 112.47,84.35 112.47,86.16 111.2,87.43 88.39,87.43 87.22,86.26 87.22,75.16 86.49,74.42 82.93,74.42 82.4,74.96 82.4,80.9 81.43,81.86 74.22,81.86 73.03,80.67 73.03,75.39 72.9,75.26 72.52,75.26 72.52,75.21 72.82,74.9 72.37,74.45 72.28,74.32 72.18,74.21 72.16,74.1 72.26,74.04 72.38,74.03 72.61,74.26 72.61,74.28 72.75,74.49 72.96,74.63 72.99,74.64 73.02,74.68 73.02,74.87 72.98,74.95 72.89,74.96 72.87,74.95 73.03,75.11 73.03,74.68 71.78,73.43 71.78,73.61 71.73,73.66 70.97,73.66 70.97,73.25 70.69,72.97 64.8,72.97 63.17,74.6 63.17,82.58 62.26,83.49 54.48,83.49 53.9,82.91 53.9,74.47 52.73,73.3 49.53,73.3 48.84,73.99 48.84,83.67 48.23,84.28 32.87,84.28 31.32,85.83 31.32,88.82
VBUS_OUT on TOP: 25.96,55.02 20.93,55.02 20.6,54.69 20.6,52.63 20.9,52.32 24.26,52.32 24.69,51.89 24.69,50.62 25.17,50.14 29.24,50.14 29.59,50.5 29.59,51.38
VBUS_OUT on BOTTOM: 39.17,66.88 39.17,69.19 39.5,69.52 42.21,69.52 42.81,68.92 42.81,66.81 42.47,66.47 39.57,66.47
VBUS_OUT on BOTTOM: 29.16,31.95 29.16,28.4 30.43,27.13 30.43,25.35 31.32,25.35 31.32,27.38 32.59,28.65 32.59,31.01 31.06,32.54 29.74,32.54
VBUS_OUT on L03_PWR: 33.15,52.04 42.9,61.8 42.9,68.68 42.09,69.49 39.67,69.49 38.56,68.38 38.56,61.32 28.96,51.71 27.23,51.71 26.11,50.6 26.11,49.5 30.07,45.54 30.07,28.91 30.51,28.47 32.66,28.47 33.15,28.96
VDD_5V on BOTTOM: 45.26,61.42 44.83,61.85 44.83,67.16 45.21,67.54 48.59,67.54 49.02,67.11 49.02,61.93 48.51,61.42
VDD_5V on L03_PWR: 104.59,32.65 105.03,33.1 105.92,33.1 106.3,32.72 106.3,30.18 106.02,29.9 104.8,29.9 104.59,30.11
VDD_REG_5V on BOTTOM: 17.09,62.05 17.09,59.13 17.48,58.75 22.3,58.75 22.81,59.26 22.81,62.05 22.3,62.56 17.6,62.56
VDD_REG_5V on BOTTOM: 49.63,64.21 49.63,61.95 50.16,61.42 52.65,61.42 53.09,61.85 53.09,64.31 52.76,64.64 50.06,64.64
VDD_REG_5V on L03_PWR: 18.14,61.24 18.14,54.08 19.86,52.35 26.64,52.35 27.08,52.78 28.02,52.78 35.56,60.33 35.56,67.94 37.97,70.36 43.87,70.36 44.65,69.57 44.65,64.14 46.23,62.56 49.63,62.56 50.8,61.39 52.73,61.39 53.37,62.03 53.37,64.8 52.65,65.51 47.88,65.51 46.81,66.57 46.81,73.03 45.59,74.24 37.74,74.24 33.17,69.67 33.17,61.39 26.57,54.79 23.37,54.79 21.08,57.07 21.08,61.24 20.45,61.87 18.77,61.87
(no net) on TOP: 125.32,89.66 149.86,89.66 153.09,88.32 154.43,85.09 154.43,5.08 153.09,1.85 149.86,0.51 5.08,0.51 1.85,1.85 0.51,5.08 0.51,85.09 1.85,88.32 5.08,89.66 33.48,89.66 33.48,83.85 45.21,83.85 45.21,89.66 114.12,89.66 114.12,84.05 125.32,84.05 ; 132 cut-outs
(no net) on BOTTOM: 0.51,85.09 1.85,88.32 5.08,89.66 149.86,89.66 153.09,88.32 154.43,85.09 154.43,67.31 154.25,67.13 153.7,67.13 153.47,67.36 153.47,67.51 153.11,67.15 153.11,66.9 153.26,66.75 154.43,66.75 154.43,5.08 153.09,1.85 149.86,0.51 5.08,0.51 1.85,1.85 0.51,5.08 ; 152 cut-outs
EXT_5V on BOTTOM: 16.33,82.25 21.36,82.25 23.19,80.42 23.19,64.21 22.3,63.32 17.73,63.32 17.09,63.96 17.09,76.91 15.75,78.26 15.75,81.66
M2_3.3V on BOTTOM: 17.09,22.05 17.09,13.67 17.81,12.95 25.12,12.95 25.7,13.54 25.7,22.12 25.27,22.56 17.6,22.56
PERI_5V on BOTTOM: 128.35,75.08 132.87,79.6 137.77,79.6 138.15,79.98 138.15,81.61 140.54,81.61 142.74,79.41 142.74,78.47 143.18,78.03 144.12,78.03 146.15,76 146.15,70.51 149.76,66.9 152.5,66.9 153.21,67.61 153.21,74.35 146.76,80.8 146.76,83.41 145.44,84.73 128.91,84.73 128.36,84.19 128.36,83.1 120.75,75.49 114.07,75.49 112.57,76.99 112.57,82.58 110.82,84.33 108.28,84.33 107.52,83.57 107.52,74.93 111.18,71.27 125.76,71.27 128.35,73.86
PERI_5V on BOTTOM: 24.33,66.75 24.33,59.64 24.84,59.13 27.81,59.13 28.33,59.65 28.33,66.76 27.74,67.36 24.94,67.36
PERI_5V on L04: 27.79,61.62 27.79,70.92 33.55,76.68 107.11,76.68 110.69,80.26 110.69,83.9 107.57,87.02 35.31,87.02 24.38,76.1 24.38,61.67 25.07,60.99 27.15,60.99 ; 4 cut-outs
USB-UART_VBUS on TOP: 20.57,57.15 20.57,55.68 20.93,55.32 27,55.32 27.38,55.7 27.38,57.23 27,57.61 21.03,57.61
USB-UART_VBUS on TOP: 29.11,79.45 36.04,79.45 36.45,79.04 42.65,79.04 42.93,78.77 42.93,77.83 42.06,76.96 39.7,76.96 39.04,76.3 29.13,76.3 28.98,76.45 28.98,79.32
USB-UART_VBUS on BOTTOM: 40.13,82.3 40.13,81.56 41.81,79.88 41.81,78.84 40.92,77.95 37.47,77.95 37.11,77.6 37.11,74.47 37.34,74.24 43.18,74.24 43.56,74.63 47.6,74.63 47.78,74.8 47.78,75.16 47.4,75.54 45.49,75.54 45.19,75.84 45.19,76.76 45.24,76.83 45.24,78.56 41.2,82.6 40.44,82.6
USB-UART_VBUS on L03_PWR: 25.98,55.32 31.93,61.26 31.93,70.26 37.12,75.45 42.41,75.45 43.13,76.17 43.13,77.9 42.39,78.64 35.46,78.64 32.78,75.96 32.78,73.88 29.92,71.02 29.92,62.59 24.69,57.35 23.65,57.35 23.06,56.77 23.06,55.65 23.39,55.32
USB-UART_VBUS on L03_PWR: 37.44,82.3 37.44,80.8 37.69,80.54 40.03,80.54 40.18,80.39 40.18,77.39 40.41,77.17 42.72,77.17 43.13,77.57 43.13,79.17 42.6,79.71 42.6,80.49 41.63,81.46 41.63,82.3 41.35,82.58 37.72,82.58
USB_PWR on TOP: 122.56,78.38 122.94,78 122.94,72.87 122.35,72.29 122.35,68.02 121.87,67.54 119.33,67.54 118.95,67.92 118.95,74.83 119.63,75.51 120.09,75.51 121.03,76.45 121.03,77.88 121.54,78.38
USB_PWR on L04: 123.09,82.02 122.33,82.78 118.41,82.78 117.91,82.27 117.91,80.82 118.54,80.19 120.47,80.19 121.26,79.4 121.26,76.91 121.54,76.63 122.78,76.63 123.09,76.94
USB_PWR on L05: 118.69,69.82 118.69,67.82 118.97,67.54 122.17,67.54 122.4,67.77 122.4,69.8 122.22,69.98 118.85,69.98
N17512813 on BOTTOM: 30.05,21.92 30.05,18.36 30.68,17.73 30.68,13.67 30.05,13.03 26.62,13.03 26.11,13.54 26.11,21.03 27,21.92
N17763461 on BOTTOM: 39.75,42.04 39.75,41.55 38.73,40.54 38.73,40.46 38.73,40.46 38.73,36.52 38.73,36.51 38.73,35.69 38.28,35.23 36.32,35.23 34.8,36.75 34.8,40.18 36.78,42.16 39.62,42.16
N17763467 on BOTTOM: 43.87,41.4 43.87,40.28 44.88,39.27 44.88,35.76 44.32,35.2 41.61,35.2 41.17,35.64 41.17,40.46 40.41,41.22 40.41,42.01 40.59,42.19 43.08,42.19
N17763650 on BOTTOM: 44.17,63.4 44.17,61.31 43.96,61.31 43.96,56.1 42.39,54.53 42.39,50.27 42.11,49.99 42.11,48.77 41.83,48.49 41.83,45.59 41.76,45.52 41.27,45.52 41.2,45.59 41.2,48.44 40.41,49.23 40.41,62.31 41.68,63.58 43.99,63.58

Small or netless copper shapes (teardrops, artwork), in the pictures only: 8 on TOP, 5 on BOTTOM, 1 on L02_GND, 4 on L04, 4 on L05

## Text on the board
BOTTOM: BOTTOM SIDE
Board Geometry/Soldermask Bottom: SOLDERMASK BOTTOM
Ref Des/Silkscreen Bottom: 3.3V | M2 VBAT | 3.6V | AUDIO OUT | uSD CARD | SILKSCREEN BOTTOM
User.Comments: C26 | C233 | C228 | C226 | C235 | C229 | 1 | 23 | 33 | J8 | 75 | USB_DP | LED1 | USB_DN | LED2 | VBAT | SYS_CLK | VBAT_60P | VDDIO | VDDIO_60P | R201 | C246 | PCIE_RDP | PCIE_RDN | PCIE_TDP | J5 | PCIE_TDN | PCIE_REFCLKP | PCIE_REFCLKN | PCIE_PERST | SDA | R56 | LPO_EXT_M2 | SCL | R54 | R74 | BT_HOST_WAKE_3P3 | PCIE_CLKREQ_L | PCIE_PME_L | U5 | BT_REG_ON_3P3 | C71 | R90 | R89 | C72 | R87 | R88 | BT_GPIO6 | WL_REG_ON_3P3 | BT_GPIO7 | C260 | C255 | C84 | C261 | R15 | C262 | C259 | C263 | C360 | C48 | R4 | C247 | R3 | R16 | U4 | R203 | R17 | R200 | R18 | R99 | R2 | R19 | R8 | R20 | R21 | R10 | R22 | R12 | R11 | R13 | R14 | R7 | R6 | R53 | R73 | R72 | R71 | R9 | R100 | R1 | R55 | FB9 | 59 | 60 | J3 | 2 | R194 | R193 | D4 | CYW955572WLEPA | 600-90808-01 REV1.0 | THE INFORMATION CONTAINED HEREIN IS CONFIDENTIAL AND | PROPRIETARY TO Infineon technologies AG AND SHALL NOT | SUCH USER POSSESSES DIRECT, WRITTEN AUTHORIZATION. | BE REPRODUCED OR DISCLOSED IN WHOLE OR IN PART OR USED | FOR ANY DESIGN, MANUFACTURE, OR OTHERWISE, EXCEPT WHEN | - | 1 OF X | 3
TOP: TOP SIDE
Board Geometry/Soldermask Top: SOLDERMASK TOP
Ref Des/Silkscreen Top: GND | BT RESET | LED1 | LED2 | WL RESET | AUTOBAUD | M2_3.3V | M2_GPIO2 | M2_GPIO1 | B_DBG_CTS | BT_DBG_TX | BT_DBG_RX | BT_DBG_RTS | OFF     ON | POWER | WL JTAG | WL UART | 600-90768-01 REV 3.0 | CYW9RPIM2BASE1 | M.2 POWER | M.2 KEY E | EXT_LPO | TXD | CTS | RXD | RTS | BT UART | MEASUREMENT | PCM_SYNC | PCM_CLK | CURRENT | PCM_OUT | PCM_IN | VBAT | PCM | TR0_TAP | TR2_TAP | TR3_TAP | TR1_TAP | CM4 POWER | ANT 1 | FAULT | CM4 ACTIVITY | ANT 2 | J35 | J38 | GND-10 | 09-TCK | 6-BT.H.W | GND-08 | 07-TMS | 5-WL.H.W | 05-TDO | GND-06 | 4-RTS | 03-TDI | GND-04 | 3-CTS | INT | VBUS_EN | 2-RXD | 01-TRST | GND-02 | 1-TXD | GPIO | FLIP | SDA | SCL | VDDIO | 1.8V | RUN_PG | GPIO_VREF | 3.3V | 08-BT_REG_ON | 07-WL_REG_ON | 06-EEPROM_nWP | 05-nRPIBOOT | 04-BT_nDis | 03-WL_nDis | 02-RUN_PG | 01-GLOBAL_EN | 5V DC INPUT | USB | CYW9RPIWIFIBT-EVK | ETHERNET | HDMI | FAN | RPI DEBUG | DEVICE USB | SILKSCREEN TOP
L02_GND: L02_GND
L03_PWR: L03_PWR
L04: L04
L05: L05
PASTEMASK_TOP: SOLDERPASTE TOP
PAGE_OUTLINE: SOLDERPASTE BOTTOM
DIMENSION: X4
User.6: GOLDMASK TOP
User.7: GOLDMASK BOTTOM
User.9: 1. 16p6 11/04/2013 F.H.: | 2. 16p6 11/13/2013 F.H.: | 3. 16p6 12/09/2013 F.H.: | 4. 16p6 07/28/2014 F.H.: | 5. 16p6 11/13/2014 F.H.: | 6. 16p6 02/19/2015 F.H.: | 7. 16p# ##/##/201# X.X.: | A. CREATED StartJob_Allegro_16p6.brd FROM StartJob_Allegro_16p5.brd | B. CREATED BOARD GEOMETRY "REV" SUBCLASS FOR TRACKING REV CHANGES TO THIS DATABASE | C. ADDED GOLDMASK FILM LAYERS | D. ADDED TOOLING HOLE SYMBOL MTGHOLE_D320N TO DATABASE | E. SET SOLDERMASK DRC CHECKING TO OFF, CLINE TO SM PAD CHECK TO NE DONE AT FINAL QC | F. CREATED STANDARD SPACING CLASSES IN CONSTRAINT MANAGER TO SUPPORT BRCM NAMING STANDARD | G. CREATED STANDARD CLASS TO CLASS SPACING FOR CRITICAL_2X AND CRITICAL_3X TO PWR | A. REFRESHED FAB STACK-UP SYMBOL THAT NOW SUPPORTS IMPEDANCE REFERENCE LAYER AND COPLANAR SPACING. | A. ADDED BOARD GEOMETRY SUBCLASSES FAB_TITLEDATA2 AND FAB_TITLEDATA3 TO SUPPORT FAB DRAWING DATA ON MECHANICAL SYMBOLS | A. UPDATED FAB_NOTES SYMBOL | A. UPDATED FAB_NOTES AND FAB_TITLE SYMBOLS TO INCORPORATE UNIFORM PART NUMBERING | B. UPDATED CONSTRAINT RULE NAMES TO REFLECT NEW BRCM PREFERRED PRACTICES DOCUMENT | A. REPLACED ASSY, REV, SER, AND BCM NUMBER TEXT AND SHAPES WITH NEW "LEGEND_" FORMAT SYMBOLS | A. REV | ALLEGRO START JOB UPDATES/REVISIONS
User.19: IFAG MUC Am Campeon 1-15 | Infineon Technologies AG | 85579 NEUBIBERG - GERMANY
User.20: NOTES: UNLESS OTHERWISE SPECIFIED | 1. SPECIFICATIONS/TOLERANCES: | 2 | 3. DRILLING: | 6. ELECTRICAL TEST: | 7 | 8. IMPEDANCE: | 9. IF PANELIZATION SPECIFICATIONS ARE PROVIDED, THE PCBS SHALL BE DELIVERED IN | A. FABRICATE PER IPC-6012, CLASS 2, USING PROVIDED DATA FILES | B. ALL SPECIFICATIONS USED SHALL BE PER THEIR LATEST REVISIONS. | C. THE DIMENSIONS OF CIRCUIT FEATURES IN THE PROVIDED DATA MAY BE ADJUSTED | D. REMOVE ALL BURRS AND BREAK SHARP EDGES, .381 [.015] MAX RADIUS. | E. PARENTHETICAL INFORMATION IS FOR REFERENCE ONLY. | F. REPAIR OF PCB DEFECTS IS NOT PERMITTED. | DIELECTRIC MATERIAL: | A. DIELECTRIC MATERIAL SHALL BE PER IPC-4101/99, /124, /126 OR /129 | B. MINIMUM DIELECTRIC THICKNESS SHALL BE .051 [.002] FOR REFERENCED STACK-UP | C. SEE LAYER STACK-UP FOR REQUIRED COPPER WEIGHTS AND THE FINISHED PCB | D. FINISHED PCB THICKNESS SHALL BE MEASURED OVER LANDS AND/OR | A. VIA DIAMETERS (TOL. = +.051/- DRILL DIAMETER [+.0020/- DRILL DIAMETER]) | B. LAYER-TO-LAYER MISREGISTRATION SHALL BE .127 [.005] MAXIMUM. | A. DESIGN VERIFICATION SHALL BE DONE PRIOR TO PCB FABRICATION USING | B. ALL PCBS SHALL BE 100% ELECTRICALLY TESTED FOR OPENS AND SHORTS | C. APPLY TEST STAMP IN NON-LEGEND AREA ON REAR SIDE OF PCB; OK TO APPLY | FINAL FINISH: | A. FINAL FINISH ON ALL EXPOSED CONDUCTORS SHALL BE IMMERSION SILVER PER | A. IMPEDANCE TOLERANCE SHALL BE +/- 10%. | B. SEE LAYER STACK-UP FOR IMPEDANCE REQUIREMENTS. | PANEL FORM. HOWEVER, THESE SPECIFICATIONS MAY BE CHANGED AS REQUIRED BY THE | CONTRACT MANUFACTURER TO SUPPORT VOLUME ASSEMBLY REQUIREMENTS. | IPC-4553, .15 - .38 MICROMETERS [6 - 15 MICROINCHES] THICK. | ONLY TO COMPENSATE FOR PROCESS TOLERANCES; ADDING, REMOVING OR RELOCATING | CIRCUIT FEATURES, INCLUDING NON-FUNCTIONAL PADS, IS NOT ALLOWED, AND THE | DESIGN OF ALL PLANE STRUCTURES MUST BE MAINTAINED TO ENSURE PROPER | ELECTRICAL PERFORMANCE. | (RoHS COMPLIANT EPOXY-GLASS). | DIMENSIONS OF.076 [.003] OR GREATER; IPC-6012 REQUIREMENTS SHALL OTHERWISE | APPLY. SINGLE-PLY CONSTRUCTION IS ALLOWED. | THICKNESS. IF SPECIFIED, 1/3 OZ. STARTING FOIL MAY BE ACHIEVED BY 1/2 OZ. | FOIL REDUCTION. | CONDUCTORS NOT COVERED BY SOLDER MASK. | SHALL BE VERIFIED BEFORE PLATING; ALL OTHER HOLE DIAMETERS SHALL BE | VERIFIED AT FINAL INSPECTION. | SUPPLIED VALOR ODB++ DATABASE, OR GERBER DATA AND AN IPC-D-356 NETLIST. | USING PROVIDED DATA. | TO PANEL RAILS IF SPACE DOES NOT PERMIT. | 600-90768-01_03.TGZ OR 600-90768-01_03.ZIP
User.21: REF | LAYER | 3/5 | 2 | --- | 4/6 | 5 | 100 | 4.0/9.7 | 4.5/6.5 | 90 | DIFF | IMP | OHMS | 4.2/6.0 | 3.7/5.2 | 5.0/5.0 | ---- | WIDTH/SPACE | TRACE
User.24: THE INFORMATION CONTAINED HEREIN IS CONFIDENTIAL AND | PROPRIETARY TO Infineon technologies AG AND SHALL NOT | BE REPRODUCED OR DISCLOSED IN WHOLE OR IN PART OR USED | FOR ANY DESIGN, MANUFACTURE, OR OTHERWISE, EXCEPT WHEN | SUCH USER POSSESSES  AUTHORIZATION FROM Infineon | 85579 NEUBIBERG - GERMANY | o | [ | .XXX | .064 | .005 | ] | .XX | .13 | .01 | ANGLES | .5 | DRAWN | ENGINEER | CHECKER | QA | PROJ. ENG. | + | - | UNLESS OTHERWISE SPECIFIED | DIMENSIONS ARE IN METRIC | WITH INCHES IN BRACKETS | Infineon Technologies AG | IFAG MUC Am Campeon 1-15 | MATERIAL | FINISH | SEE BOM | NEXT ASSY | APPLICATION | USED ON | 7 | 2 | SANTHOSH R | NIKHIL K | APPROVALS | DO NOT SCALE DRAWING | DATE | 02/23/24
User.25: POWER SUPPLY AND DEBUG UART UPDATE | ROTATE SD CARD CONNECTOR | NA | CLEU-105 | 2.0 | 3.0 | 08/24/22 | 02/23/24 | SANTHOSH R | LIKZ | CLEU | NIKHIL K | ALLEGRO BOARD FILE: 600-90768-01_03
User.27: THE INFORMATION CONTAINED HEREIN IS CONFIDENTIAL AND | PROPRIETARY TO Infineon technologies AG AND SHALL NOT | SUCH USER POSSESSES DIRECT, WRITTEN AUTHORIZATION | BE REPRODUCED OR DISCLOSED IN WHOLE OR IN PART OR USED | FOR ANY DESIGN, MANUFACTURE, OR OTHERWISE, EXCEPT WHEN
User.28: THE INFORMATION CONTAINED HEREIN IS CONFIDENTIAL AND | PROPRIETARY TO CYPRESS SEMICONDUCTOR CORPORATION AND | SHALL NOT BE REPRODUCED OR DISCLOSED IN WHOLE OR IN | EXCEPT WHEN SUCH USER POSSESSES DIRECT, WRITTEN | AUTHORIZATION FROM CYPRESS SEMICONDUCTOR CORPORATION. | PART OR USED FOR ANY DESIGN, MANUFACTURE, OR OTHERWISE
User.36: THE INFORMATION CONTAINED HEREIN IS CONFIDENTIAL AND | PROPRIETARY TO Infineon technologies AG AND SHALL NOT | SUCH USER POSSESSES DIRECT, WRITTEN AUTHORIZATION | BE REPRODUCED OR DISCLOSED IN WHOLE OR IN PART OR USED | FOR ANY DESIGN, MANUFACTURE, OR OTHERWISE, EXCEPT WHEN
User.38: IFAG MUC Am Campeon 1-15 | Infineon Technologies AG | 85579 NEUBIBERG - GERMANY
User.39: DWG NO: | REV: | LAYER: | DRAWN BY: | PROJECT: | DATE: | IFAG MUC Am Campeon 1-15 | Infineon Technologies AG | 85579 NEUBIBERG - GERMANY | 620-90768-01 | 03 | ASSEMBLY BOTTOM | SANTHOSH R | CYW9RPIM2BASE1 | 02/23/24
User.45: FIGURE | FINISHED_SIZE | 9.84 | 12.0 | 31.5 | 35.43 | 39.37 | 40.16 | 51.18 | 62.99 | 98.43 | 106.3 | 127.95 | 137.8 | 169.29 | 255.91 | 29.53 | 43.31 | 49.21 | 66.9 | 56.0x16.0 | 82.68x35.43 | 106.3x35.43 | 120.08x29.53 | 139.76x39.37 | 37.4x29.53 | ROTATION | - | 90.000 | 0.000 | DRILL CHART: TOP to BOTTOM | ALL UNITS ARE IN MILS | TOLERANCE_DRILL | +3.0/-3.0 | +2.0/-2.0 | +2.95/-2.95 | +1.97/-1.97 | PLATED | NON-PLATED | QTY | 2620 | 24 | 16 | 14 | 48 | 8 | 6 | 2 | 4 | 5 | 1
